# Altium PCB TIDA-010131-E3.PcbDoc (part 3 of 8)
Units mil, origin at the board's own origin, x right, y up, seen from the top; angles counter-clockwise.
Board outline 6889.76 x 5118.11 mil, 6 copper layers (Top Layer, GND Layer, Signal Layer 1, Signal Layer 2, PWR Layer, Bottom Layer), stack 58.5 mil thick; 758 components, 455 nets, 2194 pads, 1156 vias.
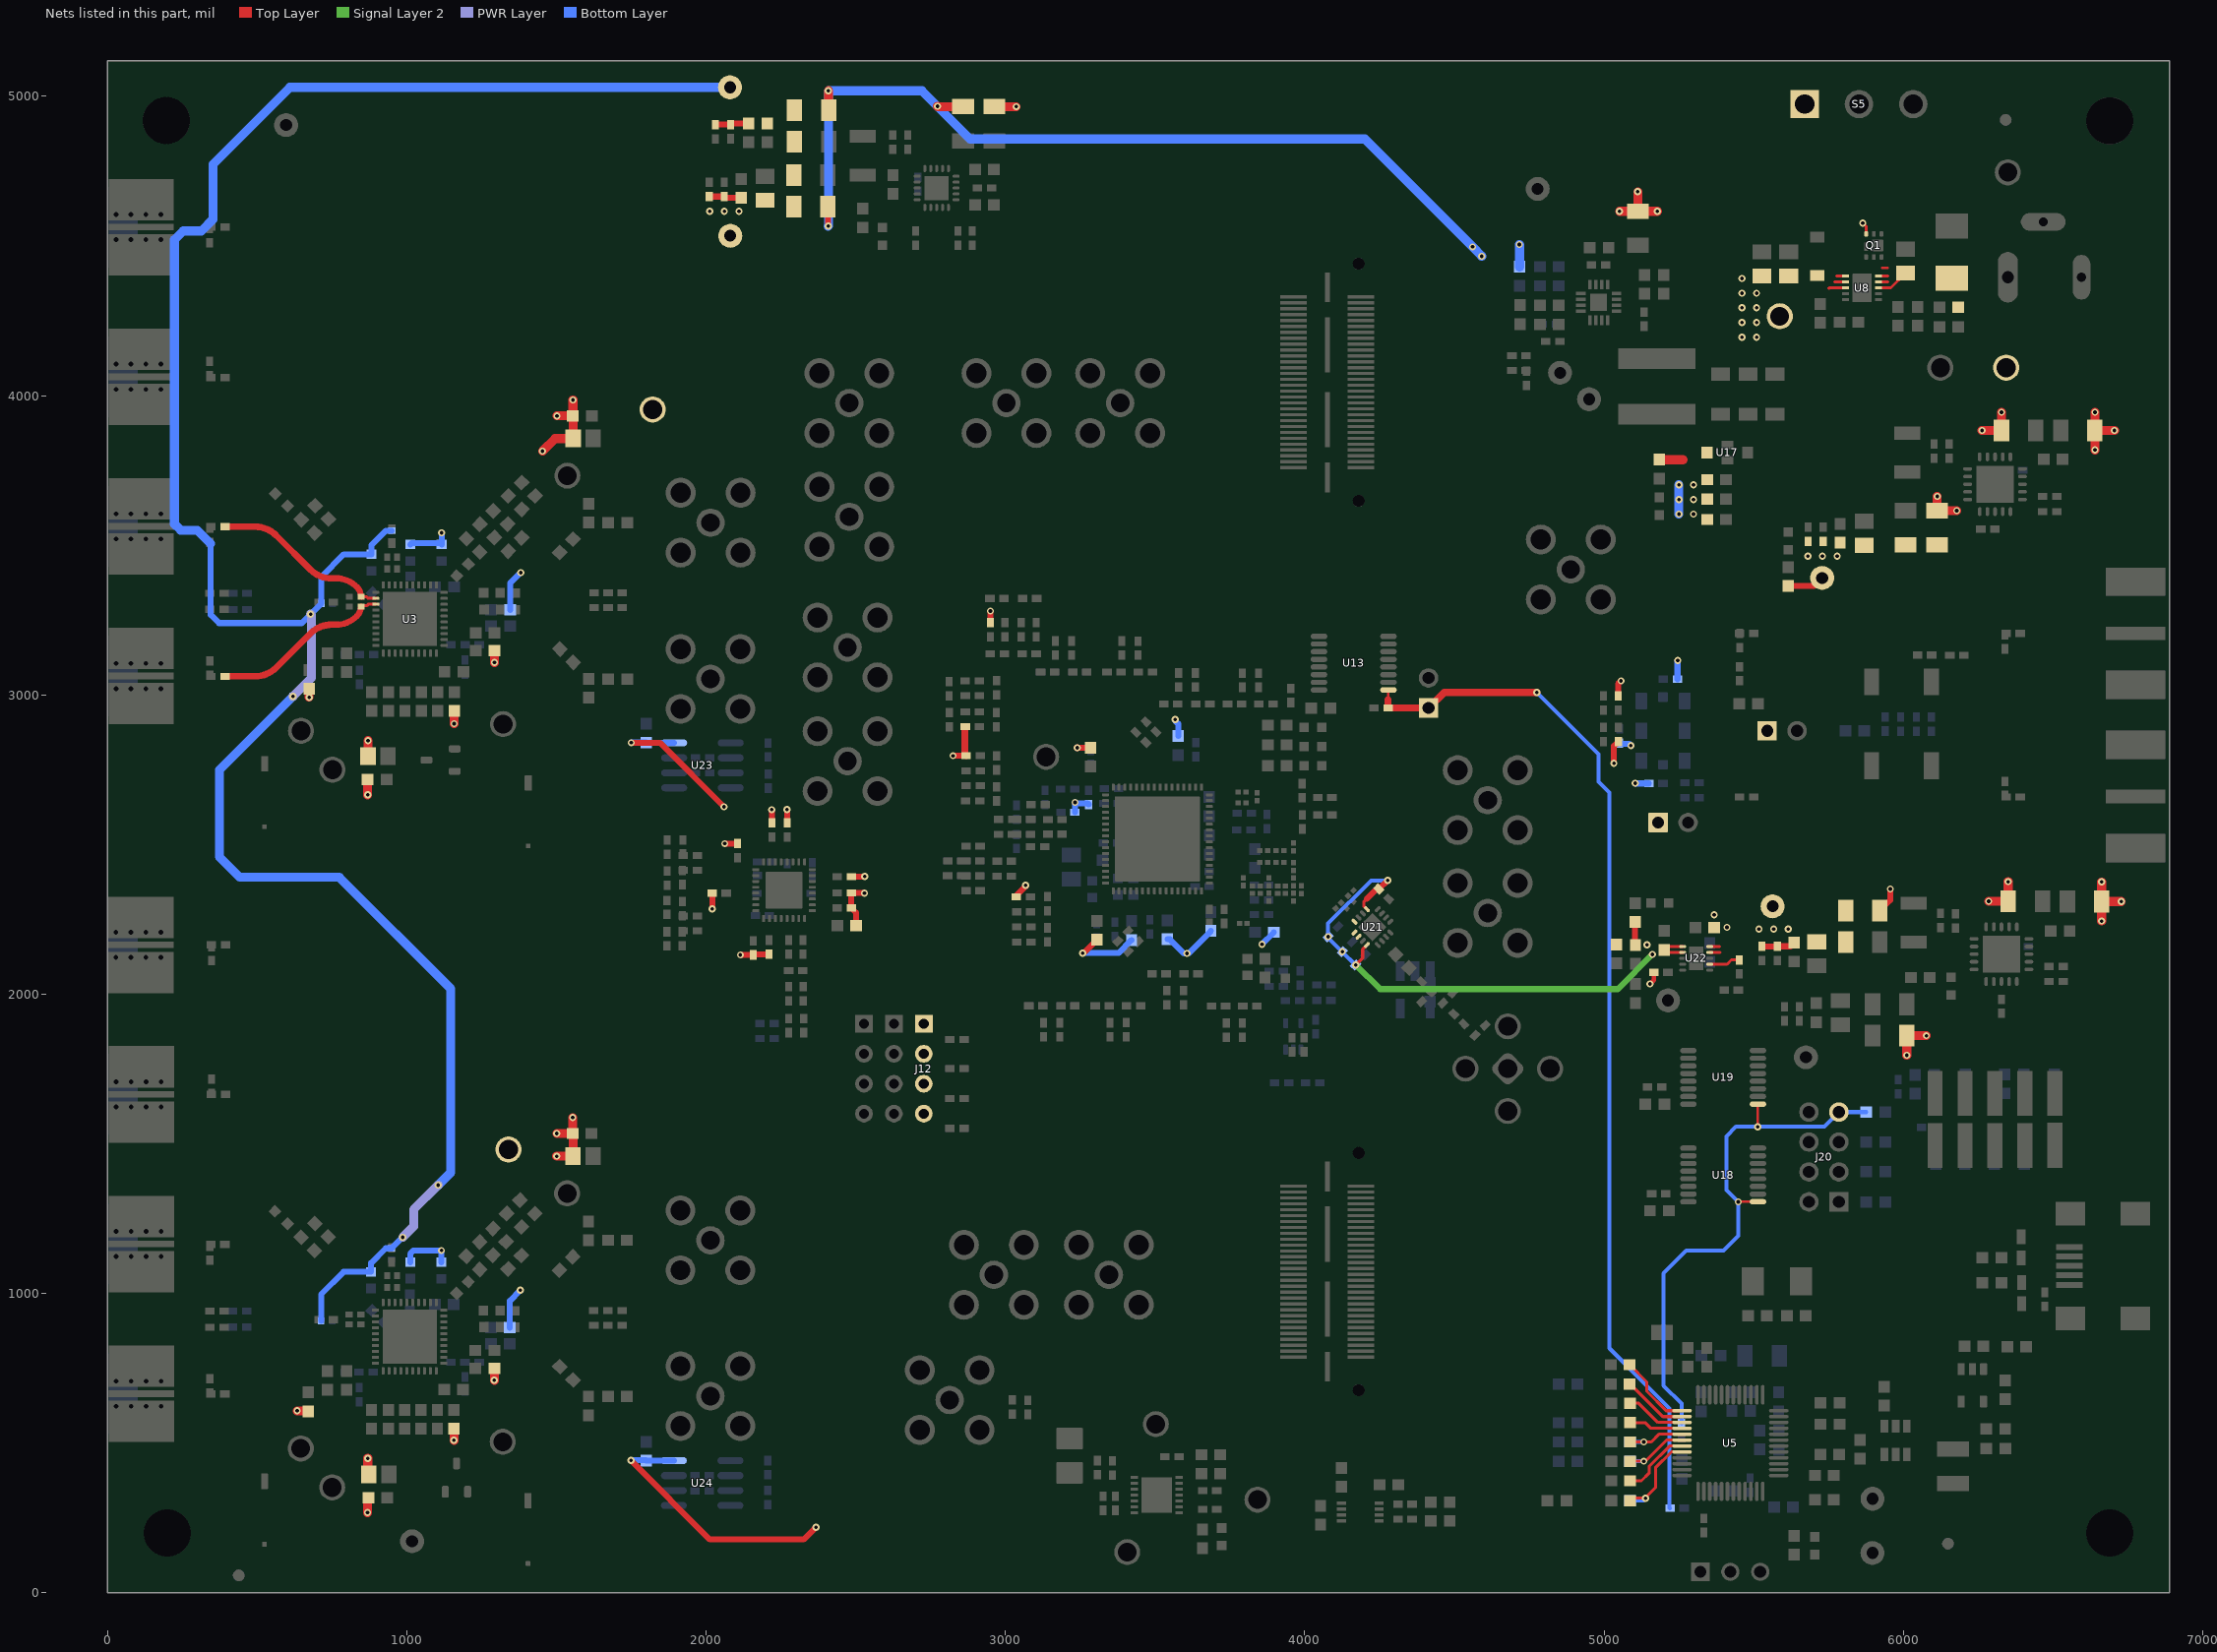
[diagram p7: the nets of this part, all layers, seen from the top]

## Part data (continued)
C11: "CAP, CERM, 12 pF, 25 V, +/- 5%, C0G/NP0, AEC-Q200 Grade 1, 0402", Cap_Case=0402, Manufacturer=Kemet, Supplier Part Number 1=399-6829-1-ND, TempCo=C0G/NP0, Tolerance_%=5, Value1=Unknown, Value2=25V, ValueDisplayed=12pF
C13: "CAP, CERM, 10uF, 10V, +/-10%, X5R, 0805", Cap_Case=0805, Manufacturer=Kemet, Supplier Part Number 1=399-4925-1-ND, TempCo=X5R, Tolerance_%=10, Value1="0.003 ohm", Value2=10V, ValueDisplayed=10µF
C17: "CAP, CERM, 0.68 µF, 10 V, +/- 10%, X5R, 0402", Cap_Case=0402, Manufacturer=TDK, Supplier Part Number 1=445-172461-1-ND, TempCo=X5R, Tolerance_%=10, Value1=Unknown, Value2=10V, ValueDisplayed=0.68µF
C18 C20 C21: "CAP, CERM, 33pF, 50V, +/-5%, C0G/NP0, 0603", Cap_Case=0603, Manufacturer=Kemet, Supplier Part Number 1=399-1055-1-ND, TempCo=C0G/NP0, Tolerance_%=5, Value1=Unknown, Value2=50V, ValueDisplayed=33pF
C19: "CAP, CERM, 100 pF, 50 V, +/- 1%, C0G/NP0, 0402", Cap_Case=0402, Manufacturer=AVX, Supplier Part Number 1=478-3658-1-ND, TempCo=C0G/NP0, Tolerance_%=1, Value1=Unknown, Value2=50V, ValueDisplayed=100pF
C24: library part grm033r60j104ke19d, "CAP, CERM, 0.1 µF, 6.3 V, +/- 10%, X5R, 0201", Cap_Case=0201, Manufacturer=MuRata, Supplier Part Number 1=490-3167-1-ND, TempCo=X5R, Tolerance_%=10, Value1=Unknown, Value2=6.3V, ValueDisplayed=0.1µF
C25 C27 C29 C30: "CAP, CERM, 0.1 µF, 6.3 V, +/- 10%, X5R, 0201", Cap_Case=0201, Manufacturer=MuRata, Supplier Part Number 1=490-3167-1-ND, TempCo=X5R, Tolerance_%=10, Value1=Unknown, Value2=6.3V, ValueDisplayed=0.1µF
C26 C28 C31 C32 C33 C34 C37 C130 C136 C140 C150 C151 C156 C161 C183: "CAP, CERM, 1 µF, 10 V, +/- 10%, X7S, 0402", Cap_Case=0402, Manufacturer=TDK, Supplier Part Number 1=445-9116-1-ND, TempCo=X7S, Tolerance_%=10, Value1="0.011416 ohm", Value2=10V, ValueDisplayed=1µF
C36 C39 C74 C116 C122 C145 C149 C166 C167 C168 C169 C170 C171 C172 C188 C197: "CAP, CERM, 0.01 µF, 25 V, +/- 10%, X7R, 0402", Cap_Case=0402, Manufacturer=MuRata, Supplier Part Number 1=490-1312-1-ND, TempCo=X7R, Tolerance_%=10, Value1=Unknown, Value2=25V, ValueDisplayed=0.01µF
C42 C43 C73: "CAP, CERM, 22 µF, 10 V, +/- 10%, X7R, 1206_190", Cap_Case=1206, Manufacturer="Wurth Elektronik", Supplier Part Number 1=732-7566-1-ND, TempCo=X7R, Tolerance_%=10, Value1=Unknown, Value2=10V, ValueDisplayed=22µF
C44 C45 C48 C57 C61 C64 C77 C78 C81 C90 C94 C97: "CAP, CERM, 0.01 µF, 16 V, +/- 10%, X7R, 0402", Cap_Case=0402, Manufacturer="AT Ceramics", Supplier Part Number 1=1284-1540-1-ND, TempCo=X7R, Tolerance_%=10, Value1=Unknown, Value2=16V, ValueDisplayed=0.01µF
C46 C47 C49 C55 C56 C63 C66 C79 C80 C82 C88 C89 C96 C99 C118 C121: "CAP, CERM, 1 µF, 16 V, +/- 10%, X7R, 0603", Cap_Case=0603, Manufacturer=TDK, Supplier Part Number 1=445-1604-1-ND, TempCo=X7R, Tolerance_%=10, Value1="0.0057 ohm", Value2=16V, ValueDisplayed=1µF
C50 C51 C54 C71 C72 C83 C84 C87 C104 C105 C192 C193: "CAP, CERM, 0.1uF, 16V, +/-5%, X7R, 0603", Alternate Manufacturer=-, Cap_Case=0603, Dielectric=X7R, DigiKeyPartNumber=478-3726-1-ND, Manufacturer=AVX, Tolerance_%=5, Value1="0.039 ohm", Value2=16V, ValueDisplayed=0.1µF
C52 C53 C85 C86: "CAP, CERM, 10uF, 10V, +/-10%, X5R, 0805", Alternate Manufacturer=-, Cap_Case=0805, Dielectric=X5R, DigiKeyPartNumber=399-4925-1-ND, Manufacturer=Kemet, Supplier Part Number 1=70K9138, Tolerance_%=10, Value1="0.003 ohm", Value2=10V, ValueDisplayed=10µF
C58 C91: "CAP, CERM, 1800 pF, 50 V,+/- 5%, C0G/NP0, 0603", Cap_Case=0603, Manufacturer=MuRata, Supplier Part Number 1=490-1457-1-ND, TempCo=C0G/NP0, Tolerance_%=5, Value2=50V, ValueDisplayed=1800pF
C59 C92: "CAP, CERM, 300pF, 100V, +/-5%, C0G/NP0, 0603", Cap_Case=0603, Manufacturer=MuRata, Supplier Part Number 1=490-1362-1-ND, TempCo=C0G/NP0, Tolerance_%=5, Value1=Unknown, Value2=100V, ValueDisplayed=300pF
C60 C93: "CAP, CERM, 0.056 µF, 50 V,+/- 10%, X7R, 0603", Cap_Case=0603, Manufacturer=MuRata, Supplier Part Number 1=81-GRM188R71H563KA93, TempCo=X7R, Tolerance_%=10, Value2=50V, ValueDisplayed=0.056µF
C62 C95: "CAP, CERM, 1500 pF, 50 V,+/- 5%, C0G/NP0, 0603", Cap_Case=0603, Manufacturer=MuRata, Supplier Part Number 1=490-11448-1-ND, TempCo=C0G/NP0, Tolerance_%=5, Value2=50V, ValueDisplayed=1500pF
C65 C67 C68 C69 C70 C98 C100 C101 C102 C103: "CAP, CERM, 10 µF, 10 V, +/- 20%, X5R, 0603", Cap_Case=0603, Manufacturer=TDK, Supplier Part Number 1=445-6853-1-ND, TempCo=X5R, Tolerance_%=20, Value1="0.0078 ohm", Value2=10V, ValueDisplayed=10µF
C75: "CAP, CERM, 0.01 µF, 25 V, +/- 10%, X7R, 0603", Cap_Case=0603, Manufacturer=MuRata, Supplier Part Number 1=490-1520-1-ND, TempCo=X7R, Tolerance_%=10, Value1=Unknown, Value2=25V, ValueDisplayed=0.01µF
C76 C106 C107 C112 C123 C129 C134 C138 C143 C147 C152 C154 C159 C163 C180 C182 C194 C195: "CAP, CERM, 10 µF, 10 V, +/- 20%, X5R, 0603", Cap_Case=0603, Manufacturer=MuRata, TempCo=X5R, Tolerance_%=20, Value1=Unknown, Value2=10V, ValueDisplayed=10µF
C119: "CAP, CERM, 100 µF, 10 V, +/- 20%, X5R, 1210", Cap_Case=1210, Manufacturer=MuRata, Supplier Part Number 1=490-9969-1-ND, TempCo=X5R, Tolerance_%=20, Value1=Unknown, Value2=10V, ValueDisplayed=100µF
C125 C126: "CAP, CERM, 27 pF, 100 V, +/- 5%, C0G/NP0, 0603", Cap_Case=0603, Manufacturer=MuRata, Supplier Part Number 1=490-1337-1-ND, TempCo=C0G/NP0, Tolerance_%=5, Value1=Unknown, Value2=100V, ValueDisplayed=27pF
C127 C128 C131: "CAP, CERM, 1 µF, 25 V, +/- 10%, X5R, 0805", Cap_Case=0805, Manufacturer=AVX, Supplier Part Number 1=478-1409-1-ND, TempCo=X5R, Tolerance_%=10, Value1="0.012 ohm", Value2=25V, ValueDisplayed=1µF
C132 C133: "CAP, CERM, 1000 pF, 100 V, +/- 20%, X7R, 0603", Cap_Case=0603, Manufacturer=AVX, Supplier Part Number 1=478-3699-1-ND, TempCo=X7R, Tolerance_%=20, Value1="0.276 ohm", Value2=100V, ValueDisplayed=1000pF
C137 C141 C157: "CAP, CERM, 47 µF, 10 V, +/- 20%, X5R, 1210", Cap_Case=1210_280, Manufacturer=TDK, Supplier Part Number 1=445-6711-1-ND, TempCo=X5R, Tolerance_%=20, Value1="0.003602 ohm", Value2=10V, ValueDisplayed=47µF
C142 C146 C158 C196: "CAP, CERM, 33 µF, 10 V, +/- 20%, X5R, 0805", Cap_Case=0805, Manufacturer=TDK, Supplier Part Number 1=445-8238-1-ND, TempCo=X5R, Tolerance_%=20, Value1="0.001694 ohm", Value2=10V, ValueDisplayed=33µF
C176: "CAP, CERM, 2200 pF, 25 V, +/- 10%, X7R, 0402", Cap_Case=0402, Manufacturer=MuRata, Supplier Part Number 1=490-5419-1-ND, TempCo=X7R, Tolerance_%=10, Value1=Unknown, Value2=25V, ValueDisplayed=2200pF
C177: "CAP, CERM, 10 pF, 50 V, +/- 5%, C0G/NP0, 0402", Cap_Case=0402, Manufacturer=MuRata, Supplier Part Number 1=81-GRM1555C1H100JA1D, TempCo=C0G/NP0, Tolerance_%=5, Value1=Unknown, Value2=50V, ValueDisplayed=10pF
C187: "CAP, CERM, 4.7 µF, 6.3 V, +/- 20%, X5R, 0402", Cap_Case=0402, Manufacturer=TDK, Supplier Part Number 1=445-7395-1-ND, TempCo=X5R, Tolerance_%=20, Value1=Unknown, Value2=6.3V, ValueDisplayed=4.7µF
C200 C203 C204: "CAP, CERM, 100 pF, 50 V, +/- 5%, C0G/NP0, 0402", Cap_Case=0402, Manufacturer=MuRata, Supplier Part Number 1=81-GRM1555C1H101JA1D, TempCo=C0G/NP0, Tolerance_%=5, Value1=Unknown, Value2=50V, ValueDisplayed=100pF
C201: "CAP, TA, 10 µF, 10 V, +/- 20%, 2.5 ohm, SMD", Cap_Case=B, Manufacturer=Vishay-Sprague, Supplier Part Number 1=718-1119-1-ND, Tolerance_%=20, Value1="2.5 ohm", Value2=10V, ValueDisplayed=10µF
C205 C206: "CAP, CERM, 10 µF, 16 V,+/- 20%, X5R, 0603", Cap_Case=0603, Manufacturer=MuRata, Supplier Part Number 1=GRM188R61C106MAALD-ND, TempCo=X5R, Tolerance_%=20, Value2=16V, ValueDisplayed=10µF
C207: "CAP, CERM, 0.01 µF, 16 V,+/- 10%, X7R, 0603", Cap_Case=0603, Manufacturer=MuRata, Supplier Part Number 1=490-1525-1-ND, TempCo=X7R, Tolerance_%=10, Value2=16V, ValueDisplayed=0.01µF
C208: "CAP, CERM, 0.1 µF, 16 V,+/- 10%, X7R, 0603", Cap_Case=0603, Manufacturer="Samsung Electro-Mechanics", Supplier Part Number 1=1276-1005-2-ND, TempCo=X7R, Tolerance_%=10, Value2=16V, ValueDisplayed=0.1µF
C209 C211 C212 C213: "CAP, CERM, 0.1 µF, 25 V,+/- 20%, X7R, 0402", Cap_Case=0402, Manufacturer=TDK, Supplier Part Number 1=445-7349-1-ND, TempCo=X7R, Tolerance_%=20, Value2=25V, ValueDisplayed=0.1µF
C210: "CAP, CERM, 0.1 µF, 25 V,+/- 5%, X7R, 0603", Cap_Case=0603, Manufacturer=Kemet, Supplier Part Number 1=399-1282-1-ND, TempCo=X7R, Tolerance_%=5, Value2=25V, ValueDisplayed=0.1µF
CE_TP1 CE_TP2 RMPCLK1 RMPCLK2 RMPDIR1 RMPDIR2 SYNC TP17 TP18 TP19 Vcc_TP1 Vcc_TP2 Vtune_TP1 Vtune_TP2: "Test Point, Compact, White, TH", Manufacturer=Keystone, Supplier Part Number 1=5007K-ND
D1 D2 D3 D4 D5 D6 D10 D11 D13 D14 D15 D17: "LED, Green, SMD", Color=green, Manufacturer=Lite-On, Supplier Part Number 1=160-1888-1-ND, Value1=W, Value2=3.2V
D7 D12: "PulseGuard ESD Suppressor, 24VDC, SMT", Manufacturer=Littelfuse, Supplier Part Number 1=F2594CT-ND
D8: "Diode, TVS, Bi, 15 V, 24.4 Vc, SMB", Manufacturer="Fairchild Semiconductor", Supplier Part Number 1=SMBJ15CAFSCT-ND, Value1=W
D9: "Diode, Schottky, 30 V, 1 A, SOD-123", Manufacturer="ON Semiconductor", Supplier Part Number 1=MBR130T1GOSCT-ND, Value1=1A, Value2=0.47V
D16: "LED, Green, SMD", Color=green, Manufacturer=Lite-On, Power_TotalModule=0.1, Supplier Part Number 1=160-1183-1-ND, Value1=0.1W, Value2=2.1V
FID1 FID2 FID3 FID4 FID5 FID6: "Fiducial mark.  There is nothing to buy or mount.", Manufacturer=N/A
J1 J3 J4 J6 J7 J9 J11 J13 J15 J21 J24 J32 OSCinM1 OSCinM2 OSCinP1 OSCinP2: "Connector, TH, SMA", Manufacturer="Emerson Network Power", Supplier Part Number 1=J500-ND
J2 J5: "Receptacle, 0.5 mm, 30x2, Gold, TH", Color=Black, Manufacturer=Samtec, Supplier Part Number 1=SAM8180-ND
J8 J16 J33: "Header, 100mil, 2x1, Gold, TH", Color=Black, Current_A=6.3, Manufacturer=Samtec, Supplier Part Number 1=SAM1029-02-ND, Voltage_V=550
J10 J12 J14: "Header, 100mil, 4x1, TH", Manufacturer=Mill-Max, Supplier Part Number 1=ED7204-ND
J17: "WR-COM Mini USB 2.0 Type AB SMT Horizontal 5 Contacts"
J18 J26 J27 J28: library part CMP-0077224-1, "Plug, 50 Ohm, Straight, SMT", Color=Gold, Manufacturer=Molex, PartNumber=0853050232, Voltage_V=335V
J19: "Header (shrouded), 100mil, 5x2, Gold, SMT", Manufacturer=FCI, Supplier Part Number 1=609-3593-ND
J20: "Header, 100mil, 4x2, Gold, TH", Color=Black, Current_A=6.3, Manufacturer=Samtec, Supplier Part Number 1=SAM1028-04-ND, Voltage_V=550
J22: library part CMP-0077743-1, "SMA, 50 Ohm, Gold, TH", Color=Gold, Manufacturer=Rosenberger, Supplier Part Number 1=476-32K101-400L5, Voltage_V=480V
J23: "Header, 2.54mm, 3x1, Tin, TH", Color=Black, Current_A=4, Manufacturer=Molex, Supplier Part Number 1=WM50016-03-ND, Voltage_V=250
J25: "Power Jack, mini, 2.1mm OD, R/A, TH", Manufacturer=Switchcraft, Supplier Part Number 1=SC1313-ND
L1 L2 L3 L4 L5 L6 L7 L8 L9 L10: "Ferrite Bead, 120 ohm @ 100 MHz, 0.5 A, 0603", Manufacturer=MuRata, Supplier Part Number 1=490-1011-1-ND, Value1="0.18 ohm", Value2=0.5A, ValueDisplayed="120 ohm"
L11 L12 L13 L14: "Inductor, Multilayer, Air Core, 18 nH, 0.3 A, 0.36 ohm, SMD", Manufacturer=MuRata, Supplier Part Number 1=490-2626-1-ND, Value1="0.36 ohm", Value2=0.3A, ValueDisplayed=18nH
L15 L16 L18 L19 L20 L21 L22 L23 L24 L25 L26 L27 L28 L29 L30 L31 L32 L33 L34: "Ferrite Bead, 120 ohm @ 100 MHz, 3.5 A, 1206", Manufacturer=MuRata, Supplier Part Number 1=490-1056-1-ND, Value1="0.02 ohm", Value2=3.5A, ValueDisplayed="120 ohm"
L17: "Ferrite Bead, 26 ohm @ 100 MHz, 6 A, 0603", Manufacturer=MuRata, Supplier Part Number 1=490-3995-1-ND, Value1="0.007 ohm", Value2=6A, ValueDisplayed="26 ohm"
L35: "Inductor, Shielded, Composite, 1.5 µH, 15 A, 0.0076 ohm, SMD", Manufacturer=Coilcraft, Value1="0.0076 ohm", Value2=15A, ValueDisplayed=1.5µH
L36: "Ferrite Bead, 120 ohm @ 100 MHz, 3 A, 0603", Manufacturer=MuRata, Supplier Part Number 1=490-3996-1-ND, Value1="0.025 ohm", Value2=3A, ValueDisplayed="120 ohm"
LBL1: library part THT-14-423-10, "Thermal Transfer Printable Labels, 0.650\" W x 0.200\" H - 10,000 per roll", Alternate Manufacturer=-, Manufacturer=Brady, Supplier Part Number 1=2065596
Logo1: library part ESD_Susceptible, "ESD Susceptible Symbol"
Logo2: library part Pb-Free
Logo3: library part FCC_disclaimer, "FCC_disclaimer"
Logo4: library part CMP-0074769-1
OSCinN OSCinP: "Connector, SMT, End launch SMA 50 ohm", Alternate Manufacturer=-, DigiKeyPartNumber=J658-ND, Manufacturer="Emerson Network Power Connectivity", Supplier Part Number 1=99F6798
Q1: "MOSFET, N-CH, 20 V, 10 A, DQK0006C (WSON-6)", Alternate Manufacturer=None, Manufacturer="Texas Instruments", Supplier Part Number 1=CSD15571Q2-ND, Value1="19.2 ohm", Value2="2.5 nC"
Q2 Q3: library part "MMBT3904, Fairchild Semiconductor", "TRANS NPN 40V 0.2A SOT-23", Manufacturer="ON Semiconductor", Supplier Part Number 1=BSR17ATR-ND, Value1="0.2 A", Value2=300
R1 R2 R3 R4 R6 R7 R9 R10 R19 R20 R25 R27 R37 R39 R41 R42 R45 R46 R54 R55 R56 R57 R62 R63 R70 R73 R81 R84 R92 R98 R99 R100 R101 R103 R108 R110 R114 R117 R125 R131 R132 R134 R137 R141 R143 R165 R168 R172 R173 R182 R183 R184 R191 R192 R193 R194 R195 R196 R197 R200 R201 R202 R208 R218 R219 R233 R234 R235 R236 R237 R238 R239 R240 R241 R242 R243 R244 R250 R251 R252 R253 R254 R255 R256 R257 R258 R259 R260 R261 R262 R263 R264 R265 R266 R267 R268 R269 R274 R275 R277 R278 R279 R280 R284 R285 R290 R291 R297 R298 R299 R300 R313 R314 R322 R325 R329 R330 R335 R336 R337 R338 R339 R340 R341 R348 R349 R350 R351 R352 R353 R354 R355 R358 R359 R360 R361 R362 R363 R364 R365: "RES, 0, 5%, 0.063 W, 0402", Manufacturer=Vishay-Dale, Power_W=0.063, Supplier Part Number 1=541-0.0JCT-ND, TempCo="200 ppm/C", Tolerance_%=5, Value1=5%, Value2=0.063W, Value_Code=0000, ValueDisplayed=0
R5 R8 R344 R345 R346 R347 R356 R357 R366 R367: "RES, 100, 1%, 0.1 W, 0402", Manufacturer=Panasonic, Power_W=0.1, Supplier Part Number 1=P100LCT-ND, TempCo="100 ppm/C", Tolerance_%=1, Value1=1%, Value2=0.1W, Value_Code=100R, ValueDisplayed=100
R11 R12 R58 R59: "RES, 220, 5%, 0.063 W, 0402", Manufacturer=Vishay-Dale, Power_W=0.063, Supplier Part Number 1=541-220JCT-ND, TempCo="200 ppm/C", Tolerance_%=5, Value1=5%, Value2=0.063W, Value_Code=220R, ValueDisplayed=220
R13 R14: "RES, 200, 1%, 0.063 W, 0402", Manufacturer=Vishay-Dale, Power_W=0.063, Supplier Part Number 1=541-200LCT-ND, TempCo="100 ppm/C", Tolerance_%=1, Value1=1%, Value2=0.063W, Value_Code=200R, ValueDisplayed=200
R15 R16 R17 R18 R23 R24 R60 R61 R64 R65 R66 R67: "RES, 240, 5%, 0.063 W, 0402", Manufacturer=Vishay-Dale, Power_W=0.063, Supplier Part Number 1=541-240JCT-ND, TempCo="200 ppm/C", Tolerance_%=5, Value1=5%, Value2=0.063W, Value_Code=240R, ValueDisplayed=240
R21 R22 R29 R30 R31 R32 R47 R48 R49 R50 R286 R287 R288 R289: "RES, 120, 5%, 0.063 W, 0402", Manufacturer=Vishay-Dale, Power_W=0.063, Supplier Part Number 1=541-120JCT-ND, TempCo="200 ppm/C", Tolerance_%=5, Value1=5%, Value2=0.063W, Value_Code=120R, ValueDisplayed=120
R26 R72 R272 R273: "RES, 49.9, 1%, 0.05 W, 0201", Manufacturer=Vishay-Dale, Power_W=0.05, Supplier Part Number 1=541-49.9AABCT-ND, TempCo="100 ppm/C", Tolerance_%=1, Value1=1%, Value2=0.05W, Value_Code=49R9, ValueDisplayed=49.9
R28: "RES, 620, 1%, 0.05 W, 0201", Manufacturer="Yageo America", Power_W=0.05, Supplier Part Number 1=YAG2348CT-ND, TempCo="200 ppm/C", Tolerance_%=1, Value1=1%, Value2=0.05W, Value_Code=620R, ValueDisplayed=620
R33 R249: "RES, 100, 1%, 0.063 W, 0402", Manufacturer=Vishay-Dale, Power_W=0.063, Supplier Part Number 1=541-100LCT-ND, TempCo="100 ppm/C", Tolerance_%=1, Value1=1%, Value2=0.063W, Value_Code=100R, ValueDisplayed=100
R34 R40: "RES, 49.9, 1%, 0.063 W, 0402", Manufacturer=Vishay-Dale, Power_W=0.063, Supplier Part Number 1=541-49.9LCT-ND, TempCo="100 ppm/C", Tolerance_%=1, Value1=1%, Value2=0.063W, Value_Code=49R9, ValueDisplayed=49.9
R35 R316 R317 R318 R343: "RES, 10.0 k, 1%, 0.1 W, 0402", Manufacturer=Panasonic, Power_W=0.1, Supplier Part Number 1=P10.0KLCT-ND, TempCo="100 ppm/C", Tolerance_%=1, Value1=1%, Value2=0.1W, Value_Code=10k0, ValueDisplayed=10.0k
R36 R38: "RES, 18, 5%, 0.063 W, 0402", Manufacturer=Vishay-Dale, Power_W=0.063, Supplier Part Number 1=541-18JCT-ND, TempCo="200 ppm/C", Tolerance_%=5, Value1=5%, Value2=0.063W, Value_Code=18R0, ValueDisplayed=18
R43 R44 R51 R209: "RES, 12 k, 5%, 0.063 W, 0402", Manufacturer=Vishay-Dale, Power_W=0.063, Supplier Part Number 1=541-12KJCT-ND, TempCo="200 ppm/C", Tolerance_%=5, Value1=5%, Value2=0.063W, Value_Code=12k0, ValueDisplayed=12k
R52: "RES, 39.0 k, 1%, 0.05 W, 0201", Manufacturer="Yageo America", Power_W=0.05, Supplier Part Number 1=YAG2641CT-ND, TempCo="200 ppm/C", Tolerance_%=1, Value1=1%, Value2=0.05W, Value_Code=39k0, ValueDisplayed=39.0k
R53: "RES, 51 ohm, 5%, 0.1W, 0603", Manufacturer=Vishay-Dale, Power_W=0.1, Supplier Part Number 1=541-51GCT-ND, TempCo="200 ppm/C", Tolerance_%=5, Value1=5%, Value2=0.1W, Value_Code=51R0
R68 R203 R227 R271 R327 R328 R333 R334: "RES, 0, 5%, 0.05 W, AEC-Q200 Grade 0, 0201", Manufacturer=Panasonic, Power_W=0.05, Supplier Part Number 1=P15979CT-ND, TempCo=ppm/C, Tolerance_%=5, Value1=5%, Value2=0.05W, Value_Code=0000, ValueDisplayed=0
R69 R204: "RES, 51, 5%, 0.05 W, 0201", Manufacturer="Yageo America", Power_W=0.05, Supplier Part Number 1=311-51NCT-ND, TempCo="200 ppm/C", Tolerance_%=5, Value1=5%, Value2=0.05W, Value_Code=51R0, ValueDisplayed=51
R71 R95 R106 R107 R111 R112 R128 R139 R140 R144 R145 R178 R211 R212 R304 R315: "RES, 0, 5%, 0.1 W, 0603", Manufacturer=Vishay-Dale, Power_W=0.1, Supplier Part Number 1=541-0.0GCT-ND, TempCo="200 ppm/C", Tolerance_%=5, Value1=5%, Value2=0.1W, Value_Code=0000, ValueDisplayed=0
R74: library part rc0201fr-07100rl, "RES, 100, 1%, 0.05 W, 0201", Manufacturer="Yageo America", Power_W=0.05, Supplier Part Number 1=311-100MCT-ND, TempCo="200 ppm/C", Tolerance_%=1, Value1=1%, Value2=0.05W, Value_Code=100R, ValueDisplayed=100
R75 R76: "RES, 294, 1%, 0.063 W, 0402", Manufacturer=Vishay-Dale, Power_W=0.063, Supplier Part Number 1=541-294LCT-ND, TempCo="100 ppm/C", Tolerance_%=1, Value1=1%, Value2=0.063W, Value_Code=294R, ValueDisplayed=294
R77 R78 R79 R80: "RES, 750, 1%, 0.1 W, 0603", Manufacturer=Vishay-Dale, Power_W=0.1, Supplier Part Number 1=541-750HCT-ND, TempCo="100 ppm/C", Tolerance_%=1, Value1=1%, Value2=0.1W, Value_Code=750R, ValueDisplayed=750
R82 R86 R93 R97 R115 R119 R126 R130: "RES, 50, 0.1%, 0.05 W, 0402", Manufacturer=Vishay-Dale, Power_W=0.05, Supplier Part Number 1=FC0402-50BWCT-ND, TempCo="25 ppm/C", Tolerance_%=0.1, Value1=0.1%, Value2=0.05W, Value_Code=50R0, ValueDisplayed=50
R83 R85 R87 R88 R89 R91 R116 R118 R120 R121 R122 R124 R148: "RES, 0 ohm, 5%, 0.1W, 0603", DigiKeyPartNumber=541-0.0GCT-ND, Manufacturer=Vishay-Dale, Power_W=0.1, Supplier Part Number 1=52K8014, Tolerance_%=5, Value1=5%, Value2=0.1W, Value_Code=0000
R90 R123: "RES, 100 k, 5%, 0.1 W, 0603", Manufacturer=Vishay-Dale, Power_W=0.1, Supplier Part Number 1=541-100KGCT-ND, TempCo="200 ppm/C", Tolerance_%=5, Value1=5%, Value2=0.1W, Value_Code=100k
R94 R127: "RES, 270, 5%, 0.1 W, 0603", Manufacturer="Yageo America", Power_W=0.1, Supplier Part Number 1=311-270GRCT-ND, TempCo="100 ppm/C", Tolerance_%=5, Value1=5%, Value2=0.1W, Value_Code=270R, ValueDisplayed=270
R96 R129: "RES, 120, 5%, 0.1 W, 0603", Manufacturer=Vishay-Dale, Power_W=0.1, Supplier Part Number 1=541-120GCT-ND, TempCo="200 ppm/C", Tolerance_%=5, Value1=5%, Value2=0.1W, Value_Code=120R, ValueDisplayed=120
R102 R109 R135 R142 R154 R156 R157 R158 R159 R181 R185 R186 R187 R188 R189 R206 R207 R225: "RES, 100, 1%, 0.1 W, 0603", Manufacturer=Vishay-Dale, Power_W=0.1, Supplier Part Number 1=541-100HCT-ND, TempCo="100 ppm/C", Tolerance_%=1, Value1=1%, Value2=0.1W, Value_Code=100R, ValueDisplayed=100
R104 R113 R138 R146: "RES, 51, 5%, 0.1 W, 0603", Manufacturer=Vishay-Dale, Power_W=0.1, Supplier Part Number 1=541-51GCT-ND, TempCo="200 ppm/C", Tolerance_%=5, Value1=5%, Value2=0.1W, Value_Code=51R0, ValueDisplayed=51
R105 R136: "RES, 330 ohm, 5%, 0.1W, 0603", DigiKeyPartNumber=311-330GRCT-ND, Manufacturer="Yageo America", Power_W=0.1, Tolerance_%=5, Value1=5%, Value2=0.1W, Value_Code=330R
R133 R276 R281 R301: "RES, 100, 5%, 0.063 W, 0402", Manufacturer=Vishay-Dale, Power_W=0.063, Supplier Part Number 1=541-100JCT-ND, TempCo="200 ppm/C", Tolerance_%=5, Value1=5%, Value2=0.063W, Value_Code=100R, ValueDisplayed=100
R147: "RES, 39 k, 5%, 0.1 W, 0603", Manufacturer=Vishay-Dale, Power_W=0.1, Supplier Part Number 1=541-39KGCT-ND, TempCo="200 ppm/C", Tolerance_%=5, Value1=5%, Value2=0.1W, Value_Code=39k0, ValueDisplayed=39k
R149 R150: "RES, 10.0, 1%, 0.25 W, 0603", Manufacturer=Vishay-Dale, Power_W=0.25, Supplier Part Number 1=541-10.0SCT-ND, TempCo="100 ppm/C", Tolerance_%=1, Value1=1%, Value2=0.25W, Value_Code=10R0, ValueDisplayed=10.0
R151 R152 R155 R160 R161 R162 R205 R308 R309 R310 R312: "RES, 10 k, 5%, 0.1 W, 0603", Manufacturer=Vishay-Dale, Power_W=0.1, Supplier Part Number 1=541-10KGCT-ND, TempCo="200 ppm/C", Tolerance_%=5, Value1=5%, Value2=0.1W, Value_Code=10k0, ValueDisplayed=10k
R153: "RES, 12k ohm, 5%, 0.1W, 0603", Manufacturer=Vishay-Dale, Power_W=0.1, Supplier Part Number 1=72M6821, Tolerance_%=5, Value1=5%, Value2=0.1W, Value_Code=12k0
R163: "RES, 2.0 k, 5%, 0.1 W, 0603", Manufacturer=Vishay-Dale, Power_W=0.1, Supplier Part Number 1=541-2.0KGCT-ND, TempCo="200 ppm/C", Tolerance_%=5, Value1=5%, Value2=0.1W, Value_Code=2k00, ValueDisplayed=2.0k
R164: "RES, 1.00 M, 1%, 0.1 W, 0603", Manufacturer=Vishay-Dale, Power_W=0.1, Supplier Part Number 1=541-1.00MHCT-ND, TempCo="100 ppm/C", Tolerance_%=1, Value1=1%, Value2=0.1W, Value_Code=1M00, ValueDisplayed=1.00M
R166: "RES, 45.3 k, 1%, 0.1 W, 0603", Manufacturer=Vishay-Dale, Power_W=0.1, Supplier Part Number 1=541-45.3KHCT-ND, TempCo="100 ppm/C", Tolerance_%=1, Value1=1%, Value2=0.1W, Value_Code=45k3, ValueDisplayed=45.3k
R167: "RES, 10.0 k, 1%, 0.1 W, 0603", Manufacturer=Vishay-Dale, Power_W=0.1, Supplier Part Number 1=541-10.0KHCT-ND, TempCo="100 ppm/C", Tolerance_%=1, Value1=1%, Value2=0.1W, Value_Code=10k0, ValueDisplayed=10.0k
R169: "RES, 100 k, 1%, 0.1 W, 0603", Manufacturer=Vishay-Dale, Power_W=0.1, Supplier Part Number 1=541-100KHCT-ND, TempCo="100 ppm/C", Tolerance_%=1, Value1=1%, Value2=0.1W, Value_Code=100k
R170 R171 R174 R175 R176 R177 R179 R180 R295: "RES, 0, 5%, 0.063 W, 0402", Manufacturer=Panasonic, Power_W=0.063, Supplier Part Number 1=P0.0JCT-ND, TempCo="600 ppm/C", Tolerance_%=5, Value1=5%, Value2=0.063W, Value_Code=0000, ValueDisplayed=0
R190: "RES, 47, 5%, 0.063 W, 0402", Manufacturer=Vishay-Dale, Power_W=0.063, Supplier Part Number 1=541-47JCT-ND, TempCo="200 ppm/C", Tolerance_%=5, Value1=5%, Value2=0.063W, Value_Code=47R0, ValueDisplayed=47
R198 R199: "RES, 130, 1%, 0.063 W, 0402", Manufacturer=Vishay-Dale, Power_W=0.063, Supplier Part Number 1=541-130LCT-ND, TempCo="100 ppm/C", Tolerance_%=1, Value1=1%, Value2=0.063W, Value_Code=130R, ValueDisplayed=130
R210 R296 R302 R303 R305 R306 R307 R311: "RES, 33, 5%, 0.1 W, 0603", Manufacturer=Vishay-Dale, Power_W=0.1, Supplier Part Number 1=541-33GCT-ND, TempCo="200 ppm/C", Tolerance_%=5, Value1=5%, Value2=0.1W, Value_Code=33R0, ValueDisplayed=33
R213 R214 R215 R216: "RES, 10.0 k, 0.5%, 0.063 W, 0402", Manufacturer=Vishay-Dale, Power_W=0.063, Supplier Part Number 1=541-10KAVCT-ND, TempCo="50 ppm/C", Tolerance_%=0.5, Value1=0.5%, Value2=0.063W, Value_Code=10k0, ValueDisplayed=10.0k
R217 R220 R222 R223 R224 R342: "RES, 1.00 k, 1%, 0.1 W, 0603", Manufacturer=Vishay-Dale, Power_W=0.1, Supplier Part Number 1=541-1.00KHCT-ND, TempCo="100 ppm/C", Tolerance_%=1, Value1=1%, Value2=0.1W, Value_Code=1k00, ValueDisplayed=1.00k
R221: "RES, 33.2 k, 1%, 0.1 W, 0603", Manufacturer=Vishay-Dale, Power_W=0.1, Supplier Part Number 1=541-33.2KHCT-ND, TempCo="100 ppm/C", Tolerance_%=1, Value1=1%, Value2=0.1W, Value_Code=33k2, ValueDisplayed=33.2k
R226: "RES, 48.7 k, 1%, 0.1 W, 0603", Manufacturer=Vishay-Dale, Power_W=0.1, Supplier Part Number 1=541-48.7KHCT-ND, TempCo="100 ppm/C", Tolerance_%=1, Value1=1%, Value2=0.1W, Value_Code=48k7, ValueDisplayed=48.7k
R228: "RES, 51.1, 1%, 0.1 W, 0603", Manufacturer=Vishay-Dale, Power_W=0.1, Supplier Part Number 1=541-51.1HCT-ND, TempCo="100 ppm/C", Tolerance_%=1, Value1=1%, Value2=0.1W, Value_Code=51R1, ValueDisplayed=51.1
R229: "RES, 100 k, 0.1%, 0.1 W, 0603", Manufacturer="Susumu Co Ltd", Power_W=0.1, Supplier Part Number 1=RG16P100KBCT-ND, TempCo="25 ppm/C", Value1=0.1%, Value2=0.1W, Value_Code=100k
R230: "RES, 31.6 k, 1%, 0.1 W, 0603", Manufacturer=Vishay-Dale, Power_W=0.1, Supplier Part Number 1=541-31.6KHCT-ND, TempCo="100 ppm/C", Tolerance_%=1, Value1=1%, Value2=0.1W, Value_Code=31k6, ValueDisplayed=31.6k
R231: "RES, 4.99 k, 1%, 0.1 W, 0603", Manufacturer=Vishay-Dale, Power_W=0.1, Supplier Part Number 1=541-4.99KHCT-ND, TempCo="100 ppm/C", Tolerance_%=1, Value1=1%, Value2=0.1W, Value_Code=4k99, ValueDisplayed=4.99k
R232: "RES, 182 k, 1%, 0.1 W, 0603", Manufacturer=Vishay-Dale, Power_W=0.1, Supplier Part Number 1=541-182KHCT-ND, TempCo="100 ppm/C", Tolerance_%=1, Value1=1%, Value2=0.1W, Value_Code=182k
R245 R246 R247 R248: "RES, 160, 5%, 0.063 W, 0402", Manufacturer=Vishay-Dale, Power_W=0.063, Supplier Part Number 1=541-160JCT-ND, TempCo="200 ppm/C", Tolerance_%=5, Value1=5%, Value2=0.063W, Value_Code=160R, ValueDisplayed=160
R270: "RES, 82.0, 1%, 0.1 W, 0603", Manufacturer="Yageo America", Power_W=0.1, Supplier Part Number 1=311-82.0HRCT-ND, TempCo="200 ppm/C", Tolerance_%=1, Value1=1%, Value2=0.1W, Value_Code=82R0, ValueDisplayed=82.0
R282 R283 R292 R293: "RES, 20.0, 1%, 0.063 W, 0402", Manufacturer=Vishay-Dale, Power_W=0.063, Supplier Part Number 1=541-20.0LCT-ND, TempCo="100 ppm/C", Tolerance_%=1, Value1=1%, Value2=0.063W, Value_Code=20R0, ValueDisplayed=20.0
R294: "RES, 47.5 k, 1%, 0.1 W, AEC-Q200 Grade 0, 0603", Manufacturer=Panasonic, Power_W=0.1, Supplier Part Number 1=P47.5KHCT-ND, TempCo="100 ppm/C", Tolerance_%=1, Value1=1%, Value2=0.1W, Value_Code=47k5, ValueDisplayed=47.5k
R319: "RES, 750, 5%, 0.1 W, 0603", Manufacturer=Vishay-Dale, Power_W=0.1, Supplier Part Number 1=541-750GCT-ND, TempCo="200 ppm/C", Tolerance_%=5, Value1=5%, Value2=0.1W, Value_Code=750R, ValueDisplayed=750
R320 R321: "RES, 1.3 k, 5%, 0.1 W, 0603", Manufacturer="Yageo America", Power_W=0.1, Supplier Part Number 1=311-1.3KGRCT-ND, TempCo="100 ppm/C", Tolerance_%=5, Value1=5%, Value2=0.1W, Value_Code=1k30, ValueDisplayed=1.3k
R323: "RES, 33 k, 5%, 0.063 W, 0402", Manufacturer=Vishay-Dale, Power_W=0.063, Supplier Part Number 1=541-33KJCT-ND, TempCo="200 ppm/C", Tolerance_%=5, Value1=5%, Value2=0.063W, Value_Code=33k0, ValueDisplayed=33k
R324 R326: "RES, 100 k, 1%, 0.063 W, 0402", Manufacturer=Vishay-Dale, Power_W=0.063, Supplier Part Number 1=541-100KLCT-ND, TempCo="100 ppm/C", Tolerance_%=1, Value1=1%, Value2=0.063W, Value_Code=100k
R331: "RES, 25.5 k, 1%, 0.1 W, 0603", Manufacturer=Vishay-Dale, Power_W=0.1, Supplier Part Number 1=541-25.5KHCT-ND, TempCo="100 ppm/C", Tolerance_%=1, Value1=1%, Value2=0.1W, Value_Code=25k5, ValueDisplayed=25.5k
R332: "RES, 11.8 k, 1%, 0.1 W, 0603", Manufacturer=Vishay-Dale, Power_W=0.1, Supplier Part Number 1=541-11.8KHCT-ND, TempCo="100 ppm/C", Tolerance_%=1, Value1=1%, Value2=0.1W, Value_Code=11k8, ValueDisplayed=11.8k
RFoutAM1 RFoutAM2 RFoutAP1 RFoutAP2 RFoutBM1 RFoutBM2 RFoutBP1 RFoutBP2: "JACK, SMA, 50 Ohm, Gold, Edge Mount", Color=Gold, Manufacturer=Johnson, Supplier Part Number 1=J808-ND, Voltage_V=170
S1 S2 S3 S4: "HEX STANDOFF SPACER, 9.53 mm", Manufacturer="Richco Plastics", Supplier Part Number 1=TCBS-6-01-ND
S5: "SWITCH SLIDE SPST 4A PCB, TH", CurrentRating_mA=4000, Manufacturer="C&K Components", Supplier Part Number 1=CKC5106-ND
T1: library part TFMR_5_TC1-1-13M+, Manufacturer=Mini-Circuits, Supplier Part Number 1=TC1-1-13MA+
TP1 TP2 TP8 TP9 TP10 TP11 TP12 TP13 TP14 TP15 TP16 TP20 VCCCORE: "Test Point, Miniature, Red, TH", Color=Red, Manufacturer=Keystone, Supplier Part Number 1=36-5000-ND
TP4 TP5: "Test Point, Multipurpose, Red, TH", Color=Red, Manufacturer=Keystone, Supplier Part Number 1=36-5010-ND
TP6: "Test Point, Multipurpose, White, TH", Color=White, Manufacturer=Keystone, Supplier Part Number 1=36-5012-ND
TP7: "Test Point, Multipurpose, Black, TH", Color=Black, Manufacturer=Keystone, Supplier Part Number 1=36-5011-ND
U1: Manufacturer="Texas Instruments", PartNumber=LMK04828BISQ
U2: library part LMK61E2-SIAR, "Ultra-Low Jitter Programmable Oscillator with Internal EEPROM, SIA0008B", Alternate Manufacturer="Texas Instruments"
U3 U4: library part LMX2594RHAR, "High Performance, Wideband PLLatinum RF Synthesizer, RHA0040A (VQFN-40)", Alternate Manufacturer="Texas Instruments"
U5: "Single Channel Hi-Speed USB to Multipurpose UART/FIFO IC, LQFP-48", Manufacturer=FTDI, Supplier Part Number 1=768-1101-1-ND
U6: "Single Output LDO, 300 mA, Fixed 3.3 V Output, 2 to 5.5 V Input, with Low IQ, 5-pin SOT-23 (DBV), -40 to 125 degC, Green (RoHS & no Sb/Br)", Alternate Manufacturer="Texas Instruments", Alternate PartNumber=Equivalent, Supplier Part Number 1=296-27895-2-ND
U7: "2K Microwire Compatible Serial EEPROM, SOT-23-6", Manufacturer=Microchip, Supplier Part Number 1=93LC56BT-I/OTCT-ND
U8: library part TPS259250DRCR, "5V, 5A, 30mO eFuse with Adjustable +/-15% Accurate Current Limit, DRC0010J (VSON-10)", Alternate Manufacturer="Texas Instruments"
U9: "IC, 2.95V To 6V Input, 3A Output, 2MHz, Synchronous SWIFT", Alternate Manufacturer=None, Manufacturer=TI
U10 U11: "36-V, 1-A, 4.17-µVRMS, RF LDO Voltage Regulator, RGW0020A (VQFN-20)", Alternate Manufacturer="Texas Instruments", Alternate PartNumber=TPS7A4700RGWT
U12: library part TPS7A8300ARGRR, "2-A, 6-uVRMS, RF, LDO Voltage Regulator, RGR0020A (VQFN-20)", Alternate Manufacturer="Texas Instruments"
U13 U18 U19: library part CMP-0086166-2, "Low-capacitance, 2:1 (SPDT) 4-channel, powered-off protection switch with 1.8 V logic, PW0016A (TSSOP-16)", Alternate Manufacturer="Texas Instruments", Alternate PartNumber=SN74CBTLV3257PWR, Operating Temperature Range="-40 to 125 C", Rating=Catalog
U14: "Single 2-Input Positive-AND Gate, DCK0005A (SOT-5)", Alternate Manufacturer="Texas Instruments", Alternate PartNumber=SN74LVC1G08DCKT
U15: "IC, SPDT Analog Switch", Alternate Manufacturer=None, Manufacturer=TI
U16: "3.1-GHz Differential Clock Buffer/Level Translator, RTV0032A (WQFN-32)", Alternate Manufacturer="Texas Instruments"
U17: "FILTER LC HIGH FREQ 27uF 1206", Manufacturer=MuRata, Supplier Part Number 1=490-6984-1-ND
U20: "Dual Remote Diode and Local Temperature Sensor with SMBus Interface and TruTherm Technology, 15-pin LLP", Manufacturer="Texas Instruments", PackageTopMarking=NS*UZXYTT*95233CI, PowerWise=Y, Supplier Part Number 1=1554778
U21: library part NB7V32M, "1.8V / 2.5V, 10GHz ÷4 Clock Divider with CML Outputs, QFN-16", Manufacturer="ON Semiconductor", Supplier Part Number 1=NB7V33MMNTXG-ND
U22: library part CMP-0077752-1, "500mA High-Accuracy Low-Noise Low-Dropout (LDO) Voltage Regulator, DSK0010A (WSON-10)", Alternate Manufacturer="Texas Instruments", Alternate PartNumber=TPS7A9001DSKT
U23 U24: "Automotive LVDS Dual Differential Line Receiver, 8-pin Narrow SOIC", Manufacturer="Texas Instruments", PackageTopMarking=NSZXTT*90LV0*28AQM, PowerWise=N
Y1: "VCXO, 100 MHz, 3.3V, SMD", Frequency="100 MHz", Frequency Stability=±20ppm, Manufacturer="Crystek Corporation", Supplier Part Number 1=744-1213-ND
Y2: "Crystal, 12Mhz, 18pF, SMD", Frequency=12MHz, Frequency Stability=±50ppm, Manufacturer="Abracon Corporation", Supplier Part Number 1=535-9100-1-ND
ZZ1: library part AssemblyNoteLabel, Alternate Manufacturer=-
ZZ2 ZZ3 ZZ4: library part AssemblyNote, Alternate Manufacturer=-

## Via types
v1: diameter 24, hole 12, Top Layer to Bottom Layer, 726 vias
v2: diameter 32, hole 16, Top Layer to Bottom Layer, 311 vias
v3: diameter 19.68, hole 7.87, Top Layer to Bottom Layer, 117 vias
v4: diameter 25, hole 10, Top Layer to Bottom Layer, 2 vias

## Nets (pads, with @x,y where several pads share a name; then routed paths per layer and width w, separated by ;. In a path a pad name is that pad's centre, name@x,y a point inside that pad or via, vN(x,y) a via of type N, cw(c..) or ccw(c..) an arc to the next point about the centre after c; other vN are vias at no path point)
5V: C131.1 D8.2 Q1.3 R164.2 S5.1 TP4.1 U8.3 U8.4 U8.5 | length 236.5
  Top Layer w8: 5929.11,4426.94 5948.06,4426.94
  Top Layer w10: v1(5864.64,4576) 5875.82,4564.82 Q1.3@5875.82,4540 ; U8.3@5917.3,4360.01 5958.18,4360.01 C131.1@6007.18,4409.01 ; U8.4@5917.3,4379.7 5948.9,4379.7 ; U8.5@5917.3,4399.38 5947.46,4399.38
  Top Layer w30: TP4.1@6343.66,4093.3 TP4.1@6347.18,4096.82
5VIN: C127.1 C128.1 D9.1 L30.1 L31.1 L33.1 L34.2 TP5.1 U8.6 U8.7 U8.8 | length 775.7
  Top Layer w10: 5750.54,4357.84 5752.71,4360.01 U8.8@5807.06,4360.01 ; 5770.88,4379.7 U8.7@5807.06,4379.7 ; 5777.67,4399.38 U8.6@5807.06,4399.38
  Top Layer w20: v1(5112.84,4681.07) v1@5112.97,4681.07 ; v1@5178.21,4615.83 v1(5178.21,4615.97) ; v1@6640.09,3818.26 v1(6640.22,3818.26) ; v1(6662.39,2374.86) v1@6662.52,2374.86 ; v1@6662.52,2244.39 v1(6662.65,2244.39) ; v1@6705.32,3883.5 v1(6705.32,3883.63) ; v1@6727.76,2309.63 v1(6727.76,2309.76)
  Top Layer w30: L33.1@2963,4965.35 v1(3036.02,4965.35) ; v1(5052.06,4615.83) L34.2@5112.97,4615.83 ; v1@5112.97,4681.07 L34.2@5112.97,4615.83 ; L34.2@5113.06,4615.75 L34.2@5112.97,4615.83 ; v1@5178.21,4615.83 L34.2@5112.97,4615.83 ; L31.1@6640,3883.41 L31.1@6640.09,3883.5 ; v1@6640.09,3818.26 L31.1@6640.09,3883.5 ; v1(6640.09,3944.41) L31.1@6640.09,3883.5 ; v1@6662.52,2244.39 L30.1@6662.52,2309.63 ; v1@6662.52,2374.86 L30.1@6662.52,2309.63 ; v1@6705.32,3883.5 L31.1@6640.09,3883.5 ; v1@6727.76,2309.63 L30.1@6662.52,2309.63
  other v1: 5460.66,4195.3 5509.66,4195.3 5460.66,4244.3 5509.66,4244.3 5460.66,4293.3 5509.66,4293.3 5460.66,4342.3 5509.66,4342.3 5460.66,4391.3
+2.5V: C206.1 C207.2 C209.2 C211.2 C212.2 C213.2 R326.1 R331.2 R342.2 U21.9 U21.12 U21.13 U21.14 U21.16 U22.1 U22.2 | length 1980.4
  Top Layer w10: v1(4171,2098) 4193.59,2120.59 4193.59,2149.84 4197,2153.24 ; 4197.09,2153.33 U21.16@4207.9,2164.15 ; U21.9@4207.9,2283.85 4197.09,2294.67 4197.09,2308.09 4208,2319 ; U22.2@5262.72,2139.48 5209.81,2139.48 C206.1@5200.99,2148.3 5211.86,2159.17 U22.1@5262.72,2159.17
  Top Layer w15: v1(5154,2034) 5166.38,2046.38 R326.1@5166.38,2073
  Top Layer w20: 4208,2319 4240.7,2351.7 C209.2@4247.3,2351.7 4248.7,2351.7 v1(4277,2380) ; R342.2@5104,2241.5 5104,2165.5 C207.2@5105,2164.5
  Signal Layer 2 w20: v1(4171,2098) 4252,2017 5046,2017 v1(5162,2133)
  Bottom Layer w13.5: C212.2@4169.59,2097.59 v1(4125.59,2141.59) 4078.09,2189.09 v1(4078.09,2192.09) 4078.09,2236.09 4222,2380 v1(4277,2380)
  other v1: 5144,2165
+3.3V_ALL: C123.2 C194.2 C195.2 L18.1 L19.1 L22.1 L24.1 L26.1 L28.2 L29.2 L32.2 R220.2 R228.2 U17.3 | length 3938.9
  Top Layer w20: L24.1@2407.38,4631.47 2407.38,4567.07 v1(2408.08,4566.37) ; L22.1@5921.52,2279.25 5956.43,2314.16 v1(5956.43,2351.63) ; v1@6011.52,1796.01 v1(6011.65,1796.01) ; v1@6076.76,1861.25 v1(6076.76,1861.38) ; L19.1@6108.24,3615.5 L19.1@6108.24,3615.63 ; v1(6262.68,3883.37) v1@6262.68,3883.5 ; v1(6285.11,2310.49) v1@6285.11,2310.63 ; v1(6350.21,2375.86) v1@6350.35,2375.86
  Top Layer w30: v1(2408.68,5018.58) 2409.38,5017.88 L26.1@2409.38,4953.47 L26.1@2421.25,4965.35 ; v1(2773.43,4966.52) 2774.6,4965.35 L32.2@2859,4965.35 ; R220.2@5184.3,3785.84 5263.84,3785.84 ; v1@6011.52,1796.01 L18.1@6011.52,1861.25 v1@6076.76,1861.25 ; v1(6113,3663) L19.1@6113,3615.5 v1@6178.24,3615.5 ; v1@6262.68,3883.5 L29.2@6327.91,3883.5 6328,3883.59 v1(6328,3944.5) ; v1@6285.11,2310.63 L28.2@6350.35,2310.63 v1@6350.35,2375.86
  Bottom Layer w30: v1(2408.08,4566.37) 2408.68,4566.96 v1(2408.68,5018.58) 2721.37,5018.58 v1(2773.43,4966.52) 2882.46,4857.49 4201.02,4857.49 4560.86,4497.66 v1(4560.86,4496.89) 4591.42,4466.32 v1(4591.42,4465.54) ; v1(4716.97,4504.66) 4717.97,4503.66 R228.2@4717.97,4430.16 ; v1(5250,3604) v1(5250,3653) v1(5250,3702)
  other v1: 5299,3604 6178.24,3615.63 5299,3653 5299,3702
+3.3V_LMX: C51.2 C52.2 C53.2 C54.2 C84.2 C85.2 C86.2 C87.2 C158.1 C159.2 C160.1 C161.1 L24.2 L25.2 R83.1 R85.1 R88.1 R89.2 R90.1 R91.2 R116.1 R118.1 R121.1 R122.2 R123.1 R124.2 TP11.1 Vcc_TP1.1 Vcc_TP2.1 | length 1666.9
  Top Layer w6: C87.2@1554.95,1533.94 C87.2@1555.98,1532.91 ; C54.2@1555.21,3932.35 C54.2@1556.24,3931.31
  Top Layer w20: C161.1@2010.48,4665.07 C160.1@2060.48,4665.07 2064.57,4660.98 C159.2@2117.29,4660.98
  Top Layer w30: v1(634,608) 669.42,608 R122.2@670.85,606.57 ; v1(674,2992.07) 674,3007.77 R89.2@674.8,3008.57 ; v1(868.85,268.1) C84.2@868.85,319.74 ; v1(869.61,2666) C51.2@869.61,2717.64 ; C85.2@869.88,397.54 v1(869.88,449.17) ; C52.2@870.64,2795.44 v1(870.64,2847.07) ; v1@1157.85,508.81 R124.2@1157.85,547.95 ; v1(1158.6,2903.78) R91.2@1158.6,2942.92 ; v1@1292.94,709.81 R123.1@1292.94,748.94 ; v1(1293.2,3108.21) R90.1@1293.2,3147.35 ; v1(1453.65,3814.55) 1495.65,3856.55 C53.2@1555.26,3856.55 ; v1(1501.27,1458.64) C86.2@1555.48,1458.64 1555.98,1458.14 C87.2@1555.98,1532.91 ; v1@1501.72,1533.94 1554.95,1533.94 v1@1554.95,1587.17 ; v1(1501.98,3932.35) C54.2@1555.21,3932.35 v1(1555.21,3985.57) ; C53.2@1556.24,3856.55 C54.2@1556.24,3931.31
  Bottom Layer w20: R121.1@1011.62,1104.7 1011.62,1132.37 1022.85,1143.6 1115.85,1143.6 R118.1@1115.85,1104.56 ; R88.1@1012.37,3502.6 1017.31,3507.55 1111.59,3507.55 R85.1@1116.6,3502.53 v1(1116.65,3541.55) ; R116.1@1344.45,885.89 1344.45,975.2 v1(1379.89,1010.64) ; R83.1@1345.21,3283.79 1345.21,3373.1 v1(1380.65,3408.55)
  other v1: 1157.35,509.31 1292.44,710.31 1115.89,1143.64 1501.22,1534.44 1554.45,1587.67 2012.05,4615.73 2061.05,4615.73 2110.05,4615.72
+3.3V_LMXRF: C163.2 C164.1 C182.2 C183.1 L11.1 L12.1 L13.1 L14.1 L26.2 L27.2 R87.1 R120.1 TP12.1 | length 7687.7
  Top Layer w20: C164.1@2031.08,4904.49 2032.08,4905.49 C183.1@2082.08,4905.49 2085.95,4909.37 C182.2@2142.08,4909.37
  PWR Layer w30: v1(620,2995) 681.91,3056.91 681.91,3266.28 v1(678.65,3269.55) ; v1(986.89,1187.64) 1023,1223.75 1023,1280 v1(1105,1362)
  Bottom Layer w20: 345,3505 345,3268 373,3240 649.1,3240 v1(678.65,3269.55) 678.65,3269.71 L11.1@714.9,3305.97 714.9,3394.9 789.91,3469.9 R87.1@881.7,3469.9 881.7,3499.6 930.63,3548.53 L12.1@949.79,3548.53 ; L13.1@714.14,908.07 714.14,997 789.15,1072 R120.1@880.95,1072 880.95,1101.7 929.88,1150.63 L14.1@949.03,1150.63 986.89,1188.49 v1(986.89,1187.64)
  Bottom Layer w30: 345,3505 300,3550 245,3550 223.82,3571.18 223.82,4520.34 253.47,4550 314,4550 352.5,4588.5 352.5,4772.5 609.92,5029.92 TP12.1@2080.13,5029.92 ; v1(620,2995) 374,2749 374,2459.04 442.38,2390.66 774.34,2390.66 1147,2018 1147,1404 v1(1105,1362)
+3.3V_VCO: C146.1 C147.2 C148.1 C149.1 J8.1 J16.1 L19.2 L21.2 R43.2 R44.2 R51.1 R222.2 TP9.1 | length 273.9
  Top Layer w20: R222.2@5615.85,3363.48 5701.41,3363.48 TP9.1@5728.73,3390.8
  Bottom Layer w20: R51.1@5052.07,2838.98 5054.39,2836.66 5083.97,2836.66 v1(5089.97,2830.66) ; v1(5103.97,2704.66) 5104.66,2703.98 R44.2@5149.83,2703.98 ; R43.2@5245.69,3052.6 5245.69,3113.98 v1(5246.31,3114.6)
  other v1: 5680.85,3463.98 5729.85,3463.98 5778.85,3463.98
+3.3VLMK: C76.1 C130.1 C152.2 C153.1 C165.1 C192.2 C193.2 C196.1 C197.1 C205.1 J12.1 J12.2 J12.3 J12.4 L1.1 L2.1 L3.1 L4.1 L5.1 L7.1 L8.1 L22.2 L23.2 R190.1 R198.1 R199.1 R233.2 R234.2 R235.2 R236.2 R237.2 R238.2 R239.2 R284.2 R290.2 R325.1 R336.2 R338.2 R343.2 TP10.1 U22.7 U22.9 U22.10 U23.8 U24.8 | length 3254.6
  Top Layer w10: U22.7@5353.27,2100.11 5411.11,2100.11 5425.62,2114.62 R325.1@5452,2114.62 ; U22.9@5353.27,2139.48 5387.49,2139.48 ; U22.10@5353.27,2159.17 5386.83,2159.17
  Top Layer w20: v1(1749,442) 2013,178 2326,178 v1(2367,219) ; v1(1750,2840) 1846,2840 v1(2060,2626) ; R234.2@2020.2,2337.41 2023.32,2334.28 2021,2331.96 v1(2021,2285) ; v1(2062.44,2503.03) R233.2@2104.82,2503.03 ; v1(2114.7,2131.28) C165.1@2157.32,2131.28 2159.32,2133.28 R239.2@2210.82,2133.28 ; v1(2219.32,2616.41) 2219.82,2615.91 R237.2@2219.82,2572.03 ; v1(2270.32,2616.91) 2270.82,2616.41 R238.2@2270.82,2572.53 ; R236.2@2485.44,2392.91 2529.32,2392.91 v1(2529.82,2393.41) ; C76.1@2501.31,2229.41 2501.31,2272.03 C130.1@2485.44,2287.91 R235.2@2485.44,2337.91 v1(2529.32,2337.91) ; v1(2824.97,2796.66) R284.2@2869.35,2796.66 ; R336.2@2950,3241.24 v1(2950,3280) ; R290.2@3036.35,2325.66 3036.35,2328.6 3067.97,2360.22 v1(3067.97,2363.66) ; v1@3240.11,2823 L5.1@3284.69,2823 ; v1(3258.72,2137.39) 3260.9,2137.39 L1.1@3305.57,2182.07 ; v1(5033,2771) 5033,2828.91 R199.1@5048.07,2843.98 ; R198.1@5047.07,2996.22 5047.07,3037.6 5056.07,3046.6 v1(5057.07,3046.6) ; C197.1@5527,2159.62 5578.5,2159.62 C153.1@5579,2160.12 5623.13,2160.12 C152.2@5635,2171.99
  Top Layer w24: R338.2@2864.37,2894.18 2864.37,2801.65 R284.2@2869.35,2796.66 ; v1(3239.72,2823.39) v1@3240.11,2823
  Bottom Layer w20: v1(1749,442) 1749.5,442.5 C193.2@1799,442.5 ; v1(1750,2840) 1750.5,2840.5 C192.2@1800,2840.5 1801,2839.5 U23.8@1893.51,2839.5 ; C193.2@1800,441.5 U24.8@1892.51,441.5 ; R190.1@3232.6,2607.66 v1(3232.6,2640.96) 3235.56,2638 3274.06,2638 R343.2@3278,2634.06 ; v1(3258.72,2137.39) 3378.22,2137.39 L2.1@3421.72,2180.89 ; L3.1@3541.57,2183.29 3549.83,2183.29 3597.11,2136 v1(3607,2136) 3611.29,2136 L7.1@3686.57,2211.29 ; v1(3567.72,2917.39) 3567.72,2913.39 3577.57,2903.54 L4.1@3577.57,2862.28 ; v1(3857.29,2167) L8.1@3897.07,2206.78
  other v1: 5517.76,2217.24 5566.76,2217.24 5615.76,2217.24 5410.69,2223.29 5368,2265
ACBUS0: J20.7 R312.2 R340.1 U18.1 U19.1 | length 1816.9
  Top Layer w8: v1@5449.03,1306.41 U18.1@5514.28,1306.41 ; v1@5514.14,1558.14 U19.1@5514.14,1632.43
  Bottom Layer w13.5: R340.1@5259,566 5259,632 5199,692 5199,1067 5275,1143 5399,1143 5448,1192 5448,1305.38 v1(5448.62,1306) 5409,1345.62 5409,1525 5441,1557 v1(5513,1557) 5735.63,1557 J20.7@5784.63,1606 R312.2@5876.5,1606
ACBUS1: J33.1 R209.1 R341.1 U13.1 | length 3489.5
  Top Layer w8: 4278.35,2983.85 4278.35,3014.76 U13.1@4280,3016.41
  Top Layer w24: 4278.35,2983.85 R209.1@4278.35,2956.39 J33.1@4413.72,2956.39 4466,3008.66 v1(4774.97,3008.66)
  Bottom Layer w13.5: v1(4774.97,3008.66) 4982,2801.63 4982,2710 5018,2674 5018,817 5219,616 5219,284.01 R341.1@5220.38,282.63
ADBUS0: R178.1 U5.13 | length 257.3
  Top Layer w10: R178.1@5085.7,762.02 5143,704.71 5143,673 5207.71,608.29 U5.13@5260.78,608.29
ADBUS1: R154.1 U5.14 | length 220.2
  Top Layer w10: R154.1@5085.7,697.52 5087.48,697.52 5196.4,588.6 U5.14@5260.78,588.6
ADBUS2: R212.1 U5.15 | length 200.6
  Top Layer w10: R212.1@5086.7,633.02 5115.98,633.02 5180.08,568.92 U5.15@5260.78,568.92
ADBUS3: R156.1 U5.16 | length 181.1
  Top Layer w10: R156.1@5087.7,568.52 5137.48,568.52 5156.77,549.23 U5.16@5260.78,549.23
ADBUS4: R151.1 R157.1 U5.17 | length 229
  Top Layer w10: R157.1@5087.7,504.02 v1(5133,504.02) 5158.02,504.02 5183.55,529.55 U5.17@5260.78,529.55
  Bottom Layer w13.5: R151.1@5087.7,504.02 v1(5133,504.02)
ADBUS5: R152.1 R158.1 U5.18 | length 247.5
  Top Layer w10: R158.1@5087.7,439.52 v1(5133,439.52) 5138.52,439.52 5208.86,509.86 U5.18@5260.78,509.86
  Bottom Layer w13.5: R152.1@5087.7,439.52 v1(5133,439.52)
ADBUS6: R159.1 U5.19 | length 234.1
  Top Layer w10: R159.1@5087.7,374.02 5125.02,374.02 5150.5,399.5 5150.5,421.5 5219.18,490.18 U5.19@5260.78,490.18
ADBUS7: R181.1 R205.1 U5.20 | length 335.2
  Top Layer w10: R181.1@5087.7,308.02 5095.68,316 v1(5139,316) 5139,318 5172,351 5172,417.67 5224.82,470.49 U5.20@5260.78,470.49
  Bottom Layer w13.5: R205.1@5087.7,308.02 5131.02,308.02 v1(5139,316)
ADC_CLK1+: C44.2 R82.1 U3.23 | length 594.9
  Top Layer w9.84: R82.1@849.38,3297.5 866.19,3297.5 871.44,3302.76 U3.23@896.53,3302.76
  Top Layer w12: 678.22,3205.27 cw(c748.93,3134.56) 678.91,3205.96 ; 833.61,3263.44 833.99,3263.82
  Top Layer w20: 771.93,3234.56 ccw(c762.9,3334.15) 833.61,3263.44 ; 833.99,3263.82 ccw(c801.69,3296.13) R82.1@847.33,3294.08
  Top Layer w22: C44.2@393.16,3061.91 493.44,3061.91 ccw(c493.44,3161.91) 564.15,3091.2 678.22,3205.27 ; 678.91,3205.96 cw(c748.93,3134.56) 721.16,3230.63 cw(c748.93,3134.56) 748.93,3234.56 771.93,3234.56
ADC_CLK1-: C48.2 R86.1 U3.22 | length 597.8
  Top Layer w9.84: R86.1@849.38,3327.7 866.19,3327.7 871.44,3322.44 U3.22@896.53,3322.44
  Top Layer w12: 678.22,3418.56 ccw(c748.93,3489.27) 678.91,3417.87 ; 833.61,3360.39 833.99,3360.01
  Top Layer w20: 771.93,3389.27 cw(c762.9,3289.68) 833.61,3360.39 ; 833.99,3360.01 cw(c801.69,3327.7) 847.33,3329.75 R86.1@849.38,3327.7
  Top Layer w22: C48.2@393.16,3561.91 493.44,3561.91 cw(c493.44,3461.91) 564.15,3532.62 678.22,3418.56 ; 678.91,3417.87 ccw(c748.93,3489.27) 721.16,3393.2 ccw(c748.93,3489.27) 748.93,3389.27 771.93,3389.27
